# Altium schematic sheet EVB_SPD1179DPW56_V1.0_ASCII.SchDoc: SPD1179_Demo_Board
size A2; Revision: V2.0; SheetNumber: 1; SheetTotal: 1
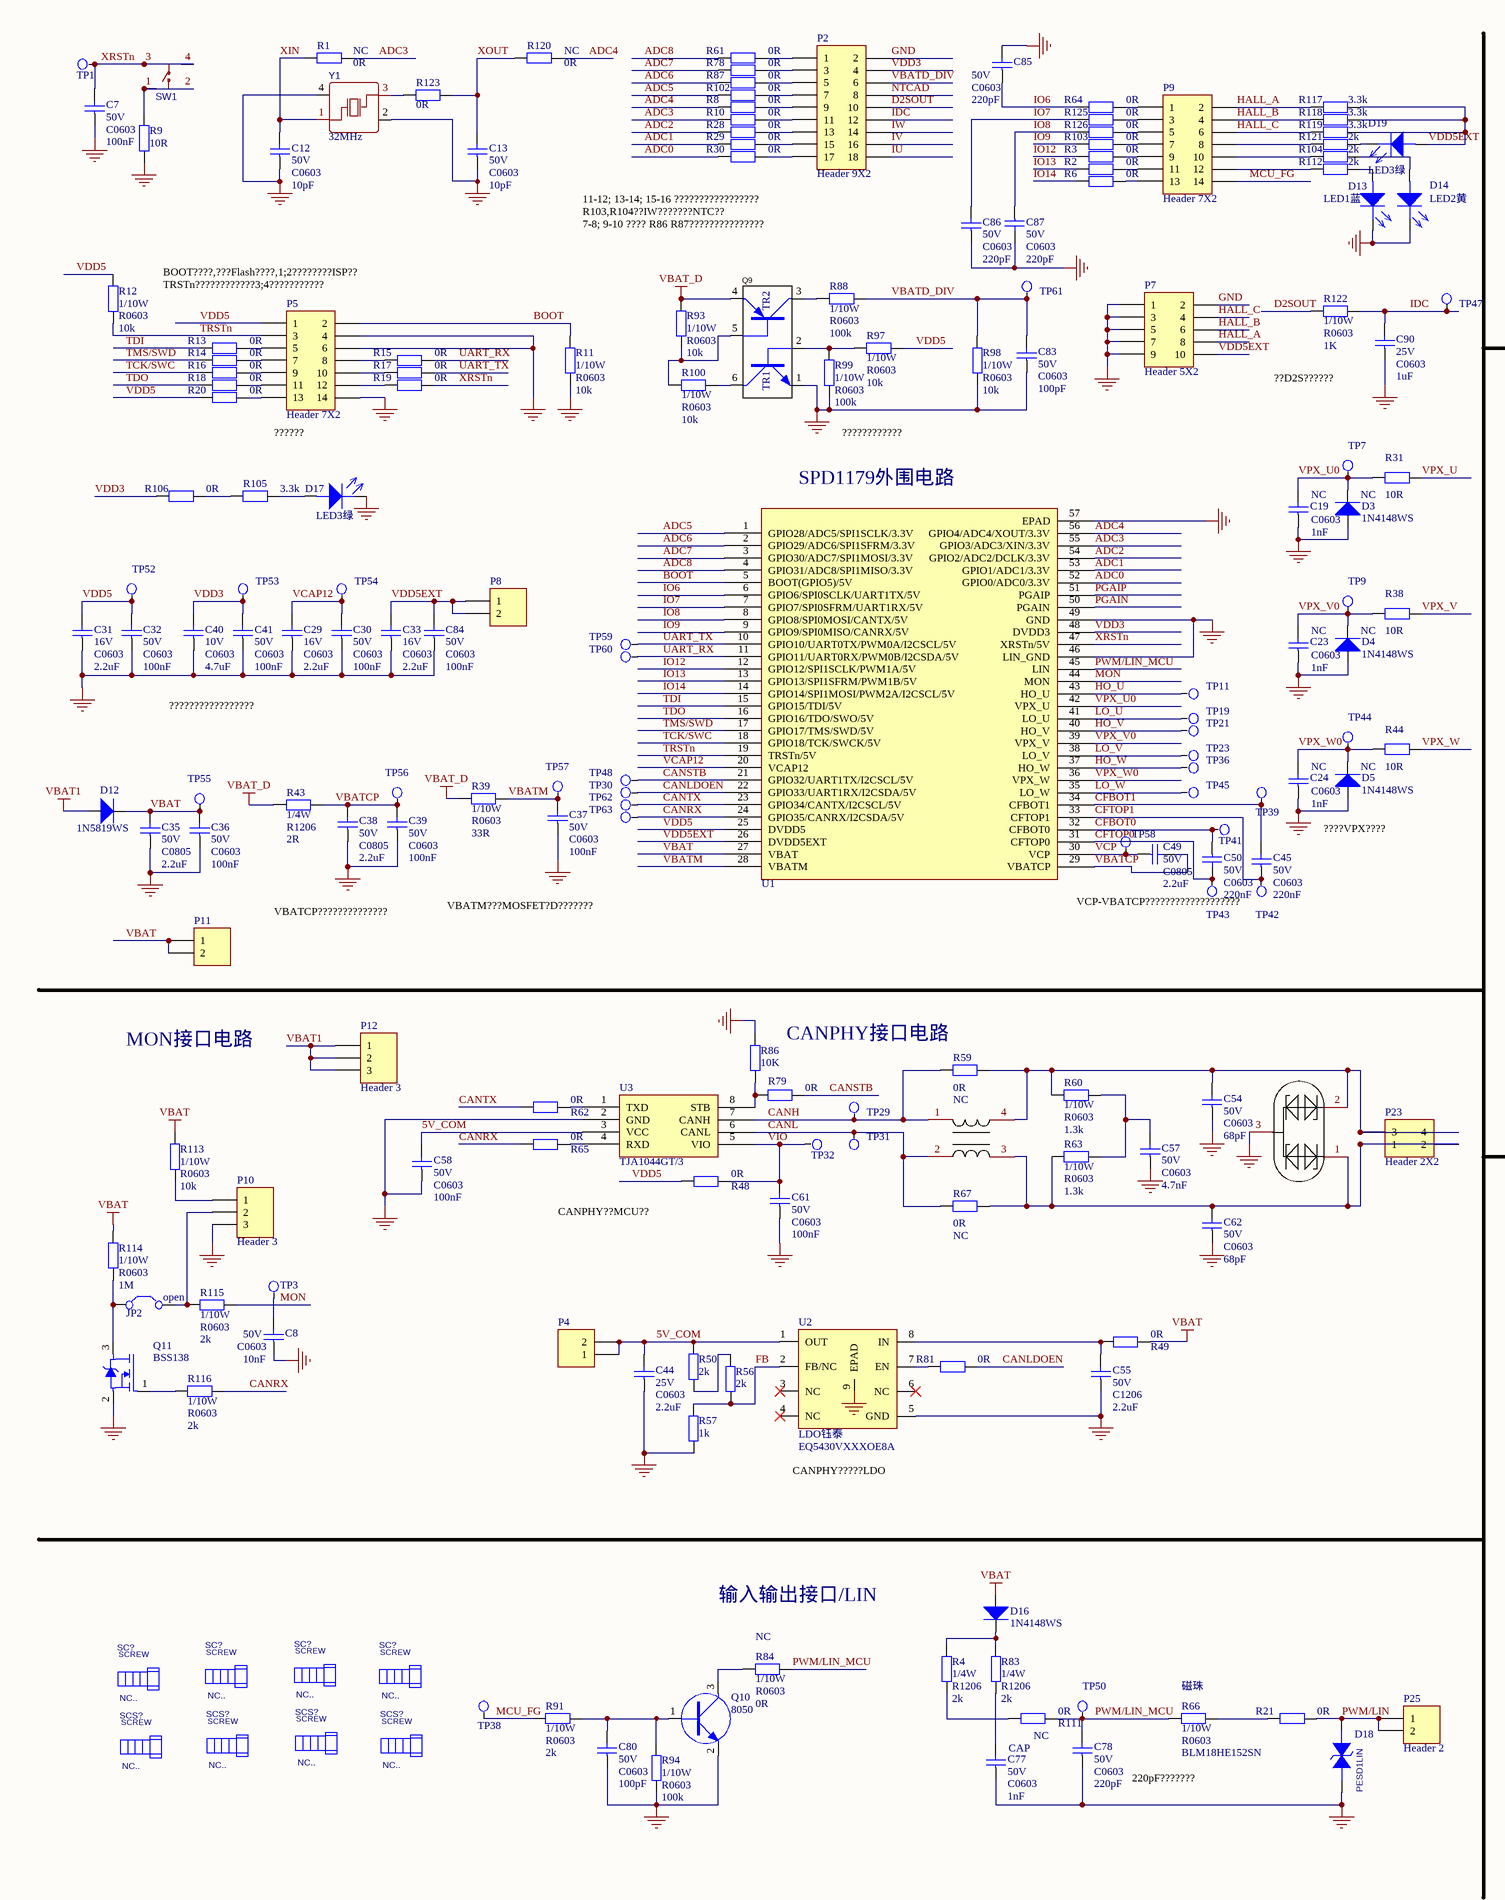
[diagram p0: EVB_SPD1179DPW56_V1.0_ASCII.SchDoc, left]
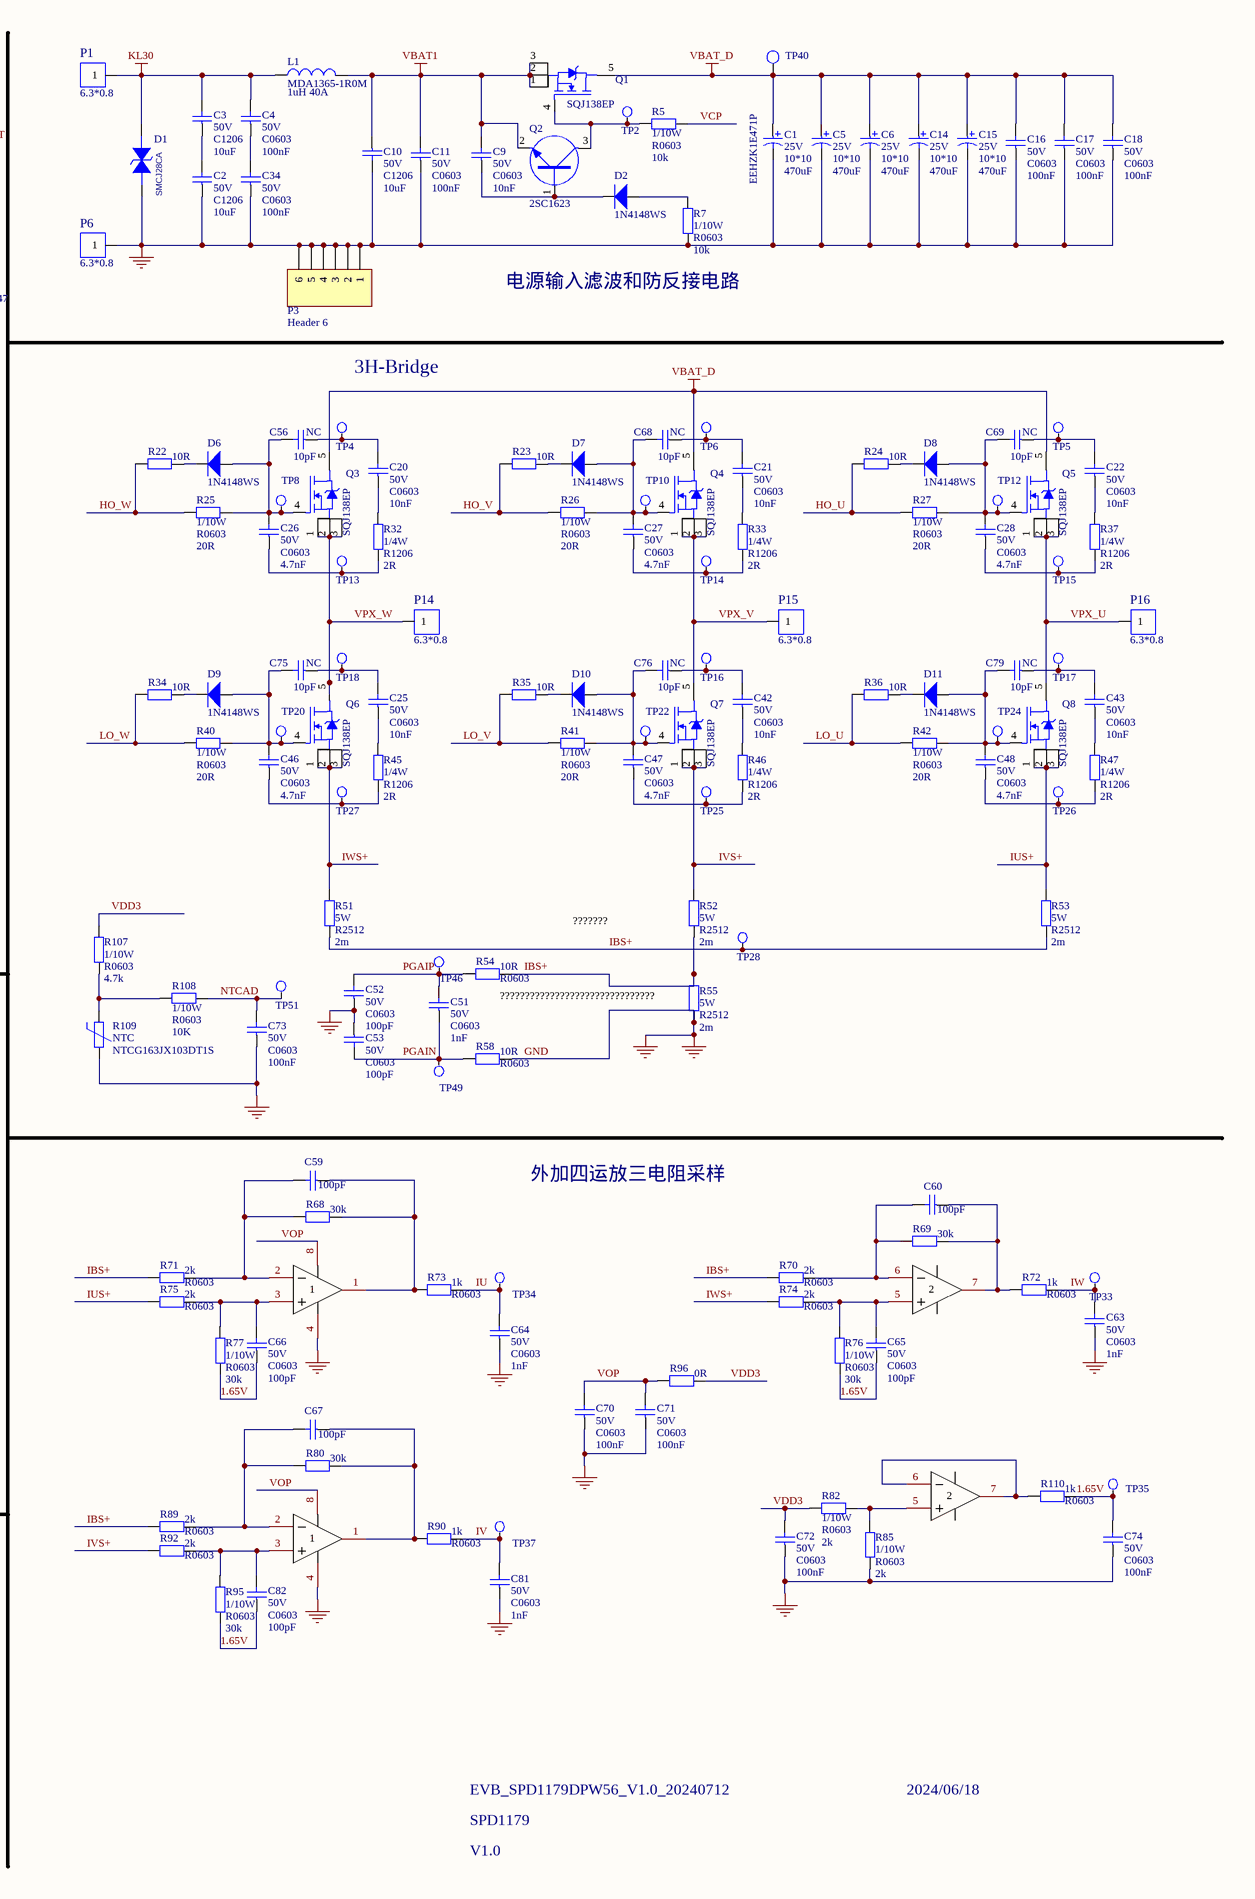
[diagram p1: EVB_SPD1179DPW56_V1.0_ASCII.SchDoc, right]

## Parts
(Parts that share a designator on the sheet are numbered #1, #2 ... from top to bottom, then left to right.)
C1  EEHZK1E471P  value 470uF  Voltage: 25V  Package: 10*10  [CAP-SMD_BD10.0-L10.3-W10.3-FD]
C2  value 10uF  Voltage: 50V  [C1206]  (hidden comment: CAP)
C3  value 10uF  Voltage: 50V  [C1206]  (hidden comment: CAP)
C4  value 100nF  Voltage: 50V  [C0603]  (hidden comment: CAP)
C5  value 470uF  Voltage: 25V  Package: 10*10  [CAP-SMD_BD10.0-L10.3-W10.3-FD]  (hidden comment: EEHZK1E471P)
C6  value 470uF  Voltage: 25V  Package: 10*10  [CAP-SMD_BD10.0-L10.3-W10.3-FD]  (hidden comment: EEHZK1E471P)
C7  value 100nF  Voltage: 50V  [C0603]  (hidden comment: CAP)
C8  value 10nF  Voltage: 50V  [C0603]  (hidden comment: CAP)
C9  value 10nF  Voltage: 50V  [C0603]  (hidden comment: CAP)
C10  value 10uF  Voltage: 50V  [C1206]  (hidden comment: CAP)
C11  value 100nF  Voltage: 50V  [C0603]  (hidden comment: CAP)
C12  value 10pF  Voltage: 50V  [C0603]  (hidden comment: CAP)
C13  value 10pF  Voltage: 50V  [C0603]  (hidden comment: CAP)
C14  value 470uF  Voltage: 25V  Package: 10*10  [CAP-SMD_BD10.0-L10.3-W10.3-FD]  (hidden comment: EEHZK1E471P)
C15  value 470uF  Voltage: 25V  Package: 10*10  [CAP-SMD_BD10.0-L10.3-W10.3-FD]  (hidden comment: EEHZK1E471P)
C16  value 100nF  Voltage: 50V  [C0603]  (hidden comment: CAP)
C17  value 100nF  Voltage: 50V  [C0603]  (hidden comment: CAP)
C18  value 100nF  Voltage: 50V  [C0603]  (hidden comment: CAP)
C19  NC  value 1nF  [C0603]
C20  value 10nF  Voltage: 50V  [C0603]  (hidden comment: CAP)
C21  value 10nF  Voltage: 50V  [C0603]  (hidden comment: CAP)
C22  value 10nF  Voltage: 50V  [C0603]  (hidden comment: CAP)
C23  NC  value 1nF  [C0603]
C24  NC  value 1nF  [C0603]
C25  value 10nF  Voltage: 50V  [C0603]  (hidden comment: CAP)
C26  value 4.7nF  Voltage: 50V  [C0603]  (hidden comment: CAP)
C27  value 4.7nF  Voltage: 50V  [C0603]  (hidden comment: CAP)
C28  value 4.7nF  Voltage: 50V  [C0603]  (hidden comment: CAP)
C29  value 2.2uF  Voltage: 16V  [C0603]  (hidden comment: CAP)
C30  value 100nF  Voltage: 50V  [C0603]  (hidden comment: CAP)
C31  value 2.2uF  Voltage: 16V  [C0603]  (hidden comment: CAP)
C32  value 100nF  Voltage: 50V  [C0603]  (hidden comment: CAP)
C33  value 2.2uF  Voltage: 16V  [C0603]  (hidden comment: CAP)
C34  value 100nF  Voltage: 50V  [C0603]  (hidden comment: CAP)
C35  value 2.2uF  Voltage: 50V  Package: C0805  [0805R]  (hidden comment: CAP)
C36  value 100nF  Voltage: 50V  [C0603]  (hidden comment: CAP)
C37  value 100nF  Voltage: 50V  [C0603]  (hidden comment: CAP)
C38  value 2.2uF  Voltage: 50V  Package: C0805  [0805R]  (hidden comment: CAP)
C39  value 100nF  Voltage: 50V  [C0603]  (hidden comment: CAP)
C40  value 4.7uF  Voltage: 10V  [C0603]  (hidden comment: CAP)
C41  value 100nF  Voltage: 50V  [C0603]  (hidden comment: CAP)
C42  value 10nF  Voltage: 50V  [C0603]  (hidden comment: CAP)
C43  value 10nF  Voltage: 50V  [C0603]  (hidden comment: CAP)
C44  value 2.2uF  Voltage: 25V  [C0603]  (hidden comment: CAP)
C45  value 220nF  Voltage: 50V  [C0603]  (hidden comment: CAP)
C46  value 4.7nF  Voltage: 50V  [C0603]  (hidden comment: CAP)
C47  value 4.7nF  Voltage: 50V  [C0603]  (hidden comment: CAP)
C48  value 4.7nF  Voltage: 50V  [C0603]  (hidden comment: CAP)
C49  value 2.2uF  Voltage: 50V  Package: C0805  [0805R]  (hidden comment: CAP)
C50  value 220nF  Voltage: 50V  [C0603]  (hidden comment: CAP)
C51  value 1nF  Voltage: 50V  [C0603]  (hidden comment: CAP)
C52  value 100pF  Voltage: 50V  [C0603]  (hidden comment: CAP)
C53  value 100pF  Voltage: 50V  [C0603]  (hidden comment: CAP)
C54  value 68pF  Voltage: 50V  [C0603]  (hidden comment: CAP)
C55  value 2.2uF  Voltage: 50V  [C1206]  (hidden comment: CAP)
C56  NC  value 10pF  [C0603]
C57  value 4.7nF  Voltage: 50V  [C0603]  (hidden comment: CAP)
C58  value 100nF  Voltage: 50V  [C0603]  (hidden comment: CAP)
C59  value 100pF  [C0603]  (hidden comment: CAP)
C60  value 100pF  [C0603]  (hidden comment: CAP)
C61  value 100nF  Voltage: 50V  [C0603]  (hidden comment: CAP)
C62  value 68pF  Voltage: 50V  [C0603]  (hidden comment: CAP)
C63  value 1nF  Voltage: 50V  [C0603]  (hidden comment: CAP)
C64  value 1nF  Voltage: 50V  [C0603]  (hidden comment: CAP)
C65  value 100pF  Voltage: 50V  [C0603]  (hidden comment: CAP)
C66  value 100pF  Voltage: 50V  [C0603]  (hidden comment: CAP)
C67  value 100pF  [C0603]  (hidden comment: CAP)
C68  NC  value 10pF  [C0603]
C69  NC  value 10pF  [C0603]
C70  value 100nF  Voltage: 50V  [C0603]  (hidden comment: CAP)
C71  value 100nF  Voltage: 50V  [C0603]  (hidden comment: CAP)
C72  value 100nF  Voltage: 50V  [C0603]  (hidden comment: CAP)
C73  value 100nF  Voltage: 50V  [C0603]  (hidden comment: CAP)
C74  value 100nF  Voltage: 50V  [C0603]  (hidden comment: CAP)
C75  NC  value 10pF  [C0603]
C76  NC  value 10pF  [C0603]
C77  CAP  value 1nF  Voltage: 50V  [C0603]
C78  value 220pF  Voltage: 50V  [C0603]  (hidden comment: CAP)
C79  NC  value 10pF  [C0603]
C80  value 100pF  Voltage: 50V  [C0603]  (hidden comment: CAP)
C81  value 1nF  Voltage: 50V  [C0603]  (hidden comment: CAP)
C82  value 100pF  Voltage: 50V  [C0603]  (hidden comment: CAP)
C83  value 100pF  Voltage: 50V  [C0603]  (hidden comment: CAP)
C84  value 100nF  Voltage: 50V  [C0603]  (hidden comment: CAP)
C85  value 220pF  Voltage: 50V  [C0603]  (hidden comment: CAP)
C86  value 220pF  Voltage: 50V  [C0603]  (hidden comment: CAP)
C87  value 220pF  Voltage: 50V  [C0603]  (hidden comment: CAP)
C90  value 1uF  Voltage: 25V  [C0603]  (hidden comment: CAP)
D1  value SMCJ28CA  [SMC/DO-214AB/Bidirect]
D2  value 1N4148WS  [SODFL2513X100/SOD323F/SC-90]  (hidden comment: DIODE)
D3  NC  value 1N4148WS  [SODFL2513X100/SOD323F/SC-90]
D4  NC  value 1N4148WS  [SODFL2513X100/SOD323F/SC-90]
D5  NC  value 1N4148WS  [SODFL2513X100/SOD323F/SC-90]
D6  value 1N4148WS  [SODFL2513X100/SOD323F/SC-90]
D7  value 1N4148WS  [SODFL2513X100/SOD323F/SC-90]
D8  value 1N4148WS  [SODFL2513X100/SOD323F/SC-90]
D9  value 1N4148WS  [SODFL2513X100/SOD323F/SC-90]
D10  value 1N4148WS  [SODFL2513X100/SOD323F/SC-90]
D11  value 1N4148WS  [SODFL2513X100/SOD323F/SC-90]
D12  value 1N5819WS  [SOD-323_L1.8-W1.3-LS2.5-RD]  (hidden comment: DIODE)
D13  value LED1蓝  [LED0603-R-RD]  (hidden comment: D_LED_0603)
D14  value LED2黄  [LED0603-R-RD]  (hidden comment: D_LED_0603)
D15  PESD1CAN,215  [SOT-23_L2.9-W1.3-P1.90-LS2.4-BR]  (value not drawn)
D16  value 1N4148WS  [SODFL2513X100/SOD323F/SC-90]
D17  value LED3绿  [LED0603-R-RD]  (hidden comment: D_LED_0603)
D18  value PESD1LIN  [SOD-323_L1.7-W1.3-LS2.5-BI]  (hidden comment: TVS)
D19  value LED3绿  [LED0603-R-RD]  (hidden comment: D_LED_0603)
JP2  open  [HDR1X2]
L1  1uH 40A  value MDA1365-1R0M  [IND-SMD_L12.6-W13.5]
L2  ACT45B-510-2P-TL003  [IND-SMD_4P-L4.5-W3.2-TL]  (value not drawn)
P1  Package: 6.3*0.8  [CON_63X08_P1]  (hidden comment: P_CON-1PIN)
P2  Header 9X2  [HDR2X9]
P3  Header 6  [HDR1X6]
P4  (no value)  [HDR1X2]
P5  Header 7X2  [HDR2X7]
P6  Package: 6.3*0.8  [CON_63X08_P1]  (hidden comment: P_CON-1PIN)
P7  Header 5X2  [HDR2X5]
P8  (no value)  [HDR1X2]
P9  Header 7X2  [HDR2X7]
P10  Header 3  [HDR1X3]
P11  (no value)  [HDR1X2]
P12  Header 3  [HDR1X3]
P14  Package: 6.3*0.8  [CON_63X08_P1]  (hidden comment: P_CON-1PIN)
P15  Package: 6.3*0.8  [CON_63X08_P1]  (hidden comment: P_CON-1PIN)
P16  Package: 6.3*0.8  [CON_63X08_P1]  (hidden comment: P_CON-1PIN)
P23  Header 2X2  [HDR2X2]
P25  Header 2  [HDR1X2]
Q1  SQJ138EP  [PowerPAK_SO-8L_3_VIS]
Q2  value 2SC1623  [SOT95P240X110-3/SOT23/TO-236]  (hidden comment: NPN)
Q3  SQJ138EP  [PowerPAK_SO-8L_3_VIS]
Q4  SQJ138EP  [PowerPAK_SO-8L_3_VIS]
Q5  SQJ138EP  [PowerPAK_SO-8L_3_VIS]
Q6  SQJ138EP  [PowerPAK_SO-8L_3_VIS]
Q7  SQJ138EP  [PowerPAK_SO-8L_3_VIS]
Q8  SQJ138EP  [PowerPAK_SO-8L_3_VIS]
Q9  BC847BPN,115  [SOT-363_L2.0-W1.3-P0.65-LS2.1-TL]  (value not drawn)
Q10  value 8050  [SOT95P240X110-3/SOT23/TO-236]  (hidden comment: NPN)
Q11  value BSS138  [SOT95P240X110-3/SOT23/TO-236]  (hidden comment: MOSFET_N-CH)
R1  NC  value 0R  [R0603]
R2  value 0R  [R0603]  (hidden comment: RES)
R3  value 0R  [R0603]  (hidden comment: RES)
R4  value 2k  Power: 1/4W  [R1206]
R5  value 10k  Power: 1/10W  [R0603]  (hidden comment: RES)
R6  value 0R  [R0603]  (hidden comment: RES)
R7  value 10k  Power: 1/10W  [R0603]  (hidden comment: RES)
R8  value 0R  [R0603]  (hidden comment: RES)
R9  value 10R  [R0603]  (hidden comment: RES)
R10  value 0R  [R0603]  (hidden comment: RES)
R11  value 10k  Power: 1/10W  [R0603]  (hidden comment: RES)
R12  value 10k  Power: 1/10W  [R0603]  (hidden comment: RES)
R13  value 0R  [R0603]  (hidden comment: RES)
R14  value 0R  [R0603]  (hidden comment: RES)
R15  value 0R  [R0603]  (hidden comment: RES)
R16  value 0R  [R0603]  (hidden comment: RES)
R17  value 0R  [R0603]  (hidden comment: RES)
R18  value 0R  [R0603]  (hidden comment: RES)
R19  value 0R  [R0603]  (hidden comment: RES)
R20  value 0R  [R0603]  (hidden comment: RES)
R21  value 0R  [R0603]  (hidden comment: RES)
R22  value 10R  [R0603]
R23  value 10R  [R0603]
R24  value 10R  [R0603]
R25  value 20R  Power: 1/10W  [R0603]
R26  value 20R  Power: 1/10W  [R0603]
R27  value 20R  Power: 1/10W  [R0603]
R28  value 0R  [R0603]  (hidden comment: RES)
R29  value 0R  [R0603]  (hidden comment: RES)
R30  value 0R  [R0603]  (hidden comment: RES)
R31  value 10R  [R0603]  (hidden comment: RES)
R32  value 2R  Power: 1/4W  [R1206]  (hidden comment: RES)
R33  value 2R  Power: 1/4W  [R1206]  (hidden comment: RES)
R34  value 10R  [R0603]
R35  value 10R  [R0603]
R36  value 10R  [R0603]
R37  value 2R  Power: 1/4W  [R1206]  (hidden comment: RES)
R38  value 10R  [R0603]  (hidden comment: RES)
R39  value 33R  Power: 1/10W  [R0603]
R40  value 20R  Power: 1/10W  [R0603]
R41  value 20R  Power: 1/10W  [R0603]
R42  value 20R  Power: 1/10W  [R0603]
R43  value 2R  Power: 1/4W  [R1206]  (hidden comment: RES)
R44  value 10R  [R0603]  (hidden comment: RES)
R45  value 2R  Power: 1/4W  [R1206]  (hidden comment: RES)
R46  value 2R  Power: 1/4W  [R1206]  (hidden comment: RES)
R47  value 2R  Power: 1/4W  [R1206]  (hidden comment: RES)
R48  value 0R  [R0603]  (hidden comment: RES)
R49  value 0R  [R0603]  (hidden comment: RES)
R50  value 2k  [R0603]  (hidden comment: RES)
R51  value 2m  Power: 5W  [R2512]  (hidden comment: RES)
R52  value 2m  Power: 5W  [R2512]  (hidden comment: RES)
R53  value 2m  Power: 5W  [R2512]  (hidden comment: RES)
R54  value 10R  [R0603]  (hidden comment: RES)
R55  value 2m  Power: 5W  [R2512]  (hidden comment: RES)
R56  value 2k  [R0603]  (hidden comment: RES)
R57  value 1k  [R0603]  (hidden comment: RES)
R58  value 10R  [R0603]  (hidden comment: RES)
R59  NC  value 0R  [R0402]
R60  value 1.3k  Power: 1/10W  [R0603]  (hidden comment: RES)
R61  value 0R  [R0603]  (hidden comment: RES)
R62  value 0R  [R0603]  (hidden comment: RES)
R63  value 1.3k  Power: 1/10W  [R0603]  (hidden comment: RES)
R64  value 0R  [R0603]  (hidden comment: RES)
R65  value 0R  [R0603]  (hidden comment: RES)
R66  磁珠  value BLM18HE152SN  Power: 1/10W  [R0603]
R67  NC  value 0R  [R0402]
R68  value 30k  [R0603]  (hidden comment: RES)
R69  value 30k  [R0603]  (hidden comment: RES)
R70  value 2k  [R0603]  (hidden comment: RES)
R71  value 2k  [R0603]  (hidden comment: RES)
R72  value 1k  [R0603]  (hidden comment: RES)
R73  value 1k  [R0603]  (hidden comment: RES)
R74  value 2k  [R0603]  (hidden comment: RES)
R75  value 2k  [R0603]  (hidden comment: RES)
R76  value 30k  Power: 1/10W  [R0603]  (hidden comment: RES)
R77  value 30k  Power: 1/10W  [R0603]  (hidden comment: RES)
R78  value 0R  [R0603]  (hidden comment: RES)
R79  value 0R  [R0603]  (hidden comment: RES)
R80  value 30k  [R0603]  (hidden comment: RES)
R81  value 0R  [R0603]  (hidden comment: RES)
R82  value 2k  Power: 1/10W  [R0603]  (hidden comment: RES)
R83  value 2k  Power: 1/4W  [R1206]
R84  NC  value 0R  Power: 1/10W  [R0603]
R85  value 2k  Power: 1/10W  [R0603]  (hidden comment: RES)
R86  value 10K  [R0603]  (hidden comment: RES)
R87  value 0R  [R0603]  (hidden comment: RES)
R88  value 100k  Power: 1/10W  [R0603]  (hidden comment: RES)
R89  value 2k  [R0603]  (hidden comment: RES)
R90  value 1k  [R0603]  (hidden comment: RES)
R91  value 2k  Power: 1/10W  [R0603]  (hidden comment: RES)
R92  value 2k  [R0603]  (hidden comment: RES)
R93  value 10k  Power: 1/10W  [R0603]  (hidden comment: RES)
R94  value 100k  Power: 1/10W  [R0603]  (hidden comment: RES)
R95  value 30k  Power: 1/10W  [R0603]  (hidden comment: RES)
R96  value 0R  [R0603]
R97  value 10k  Power: 1/10W  [R0603]  (hidden comment: RES)
R98  value 10k  Power: 1/10W  [R0603]  (hidden comment: RES)
R99  value 100k  Power: 1/10W  [R0603]  (hidden comment: RES)
R100  value 10k  Power: 1/10W  [R0603]  (hidden comment: RES)
R102  value 0R  [R0603]  (hidden comment: RES)
R103  value 0R  [R0603]  (hidden comment: RES)
R104  value 2k  [R0603]  (hidden comment: RES)
R105  value 3.3k  [R0603]  (hidden comment: RES)
R106  value 0R  [R0603]  (hidden comment: RES)
R107  value 4.7k  Power: 1/10W  [R0603]  (hidden comment: RES)
R108  value 10K  Power: 1/10W  [R0603]  (hidden comment: RES)
R109  NTC  value NTCG163JX103DT1S  [R0603]
R110  value 1k  [R0603]  (hidden comment: RES)
R111  NC  value 0R  [R0603]
R112  value 2k  [R0603]  (hidden comment: RES)
R113  value 10k  Power: 1/10W  [R0603]  (hidden comment: RES)
R114  value 1M  Power: 1/10W  [R0603]
R115  value 2k  Power: 1/10W  [R0603]  (hidden comment: RES)
R116  value 2k  Power: 1/10W  [R0603]  (hidden comment: RES)
R117  value 3.3k  [R0603]  (hidden comment: RES)
R118  value 3.3k  [R0603]  (hidden comment: RES)
R119  value 3.3k  [R0603]  (hidden comment: RES)
R120  NC  value 0R  [R0603]
R121  value 2k  [R0603]  (hidden comment: RES)
R122  value 1K  Power: 1/10W  [R0603]  (hidden comment: RES)
R123  value 0R  [R0603]  (hidden comment: RES)
R125  value 0R  [R0603]  (hidden comment: RES)
R126  value 0R  [R0603]  (hidden comment: RES)
SC?#1  value NC..  [SCREW_HOLE_Φ3_plated_wo keepout]  (hidden comment: SCREW)
SC?#2  value NC..  [SCREW_HOLE_Φ3_plated_wo keepout]  (hidden comment: SCREW)
SC?#3  value NC..  [SCREW_HOLE_Φ3_plated_wo keepout]  (hidden comment: SCREW)
SC?#4  value NC..  [SCREW_HOLE_Φ3_plated_wo keepout]  (hidden comment: SCREW)
SCS?#1  value NC..  [SCREW_SILK2]  (hidden comment: SCREW)
SCS?#2  value NC..  [SCREW_SILK2]  (hidden comment: SCREW)
SCS?#3  value NC..  [SCREW_SILK2]  (hidden comment: SCREW)
SCS?#4  value NC..  [SCREW_SILK2]  (hidden comment: SCREW)
SW1  TS-1095PD-A6B2-D2  [KEY-TH_4P-L6.0-W6.0-P3.90-LS6.5]  (value not drawn)
TP1  TEST-Point  [TP-1.0]  (value not drawn)
TP2  TEST-Point  [TP-1.0]  (value not drawn)
TP3  TEST-Point  [TP-1.0]  (value not drawn)
TP4  TEST-Point  [TP-1.0]  (value not drawn)
TP5  TEST-Point  [TP-1.0]  (value not drawn)
TP6  TEST-Point  [TP-1.0]  (value not drawn)
TP7  TEST-Point  [TP-1.0]  (value not drawn)
TP8  TEST-Point  [TP-1.0]  (value not drawn)
TP9  TEST-Point  [TP-1.0]  (value not drawn)
TP10  TEST-Point  [TP-1.0]  (value not drawn)
TP11  TEST-Point  [TP-1.0]  (value not drawn)
TP12  TEST-Point  [TP-1.0]  (value not drawn)
TP13  TEST-Point  [TP-1.0]  (value not drawn)
TP14  TEST-Point  [TP-1.0]  (value not drawn)
TP15  TEST-Point  [TP-1.0]  (value not drawn)
TP16  TEST-Point  [TP-1.0]  (value not drawn)
TP17  TEST-Point  [TP-1.0]  (value not drawn)
TP18  TEST-Point  [TP-1.0]  (value not drawn)
TP19  TEST-Point  [TP-1.0]  (value not drawn)
TP20  TEST-Point  [TP-1.0]  (value not drawn)
TP21  TEST-Point  [TP-1.0]  (value not drawn)
TP22  TEST-Point  [TP-1.0]  (value not drawn)
TP23  TEST-Point  [TP-1.0]  (value not drawn)
TP24  TEST-Point  [TP-1.0]  (value not drawn)
TP25  TEST-Point  [TP-1.0]  (value not drawn)
TP26  TEST-Point  [TP-1.0]  (value not drawn)
TP27  TEST-Point  [TP-1.0]  (value not drawn)
TP28  TEST-Point  [TP-1.0]  (value not drawn)
TP29  TEST-Point  [TP-1.0]  (value not drawn)
TP30  TEST-Point  [TP-1.0]  (value not drawn)
TP31  TEST-Point  [TP-1.0]  (value not drawn)
TP32  TEST-Point  [TP-1.0]  (value not drawn)
TP33  TEST-Point  [TP-1.0]  (value not drawn)
TP34  TEST-Point  [TP-1.0]  (value not drawn)
TP35  TEST-Point  [TP-1.0]  (value not drawn)
TP36  TEST-Point  [TP-1.0]  (value not drawn)
TP37  TEST-Point  [TP-1.0]  (value not drawn)
TP38  TEST-Point  [TP-1.0]  (value not drawn)
TP39  TEST-Point  [TP-1.0]  (value not drawn)
TP40  TEST-SMD  [TEST-SMD_L2.7-W1.0]  (value not drawn)
TP41  TEST-Point  [TP-1.0]  (value not drawn)
TP42  TEST-Point  [TP-1.0]  (value not drawn)
TP43  TEST-Point  [TP-1.0]  (value not drawn)
TP44  TEST-Point  [TP-1.0]  (value not drawn)
TP45  TEST-Point  [TP-1.0]  (value not drawn)
TP46  TEST-Point  [TP-1.0]  (value not drawn)
TP47  TEST-Point  [TP-1.0]  (value not drawn)
TP48  TEST-Point  [TP-1.0]  (value not drawn)
TP49  TEST-Point  [TP-1.0]  (value not drawn)
TP50  TEST-Point  [TP-1.0]  (value not drawn)
TP51  TEST-Point  [TP-1.0]  (value not drawn)
TP52  TEST-Point  [TP-1.0]  (value not drawn)
TP53  TEST-Point  [TP-1.0]  (value not drawn)
TP54  TEST-Point  [TP-1.0]  (value not drawn)
TP55  TEST-Point  [TP-1.0]  (value not drawn)
TP56  TEST-Point  [TP-1.0]  (value not drawn)
TP57  TEST-Point  [TP-1.0]  (value not drawn)
TP58  TEST-Point  [TP-1.0]  (value not drawn)
TP59  TEST-Point  [TP-1.0]  (value not drawn)
TP60  TEST-Point  [TP-1.0]  (value not drawn)
TP61  TEST-Point  [TP-1.0]  (value not drawn)
TP62  TEST-Point  [TP-1.0]  (value not drawn)
TP63  TEST-Point  [TP-1.0]  (value not drawn)
U1  SPD1179  [QFN-56-0.5_B]  (value not drawn)
U2  LDO钰泰  value EQ5430VXXXOE8A  [ESOP-8_L4.9-W3.9-P1.27-LS6.0-BL-EP]
U3  TJA1044GT/3  [SOIC-8_L4.9-W3.9-P1.27-LS6.0-BL]
U4  AD8542ARZ-REEL7  [SOIC-8_L4.9-W3.9-P1.27-LS6.0-BL]  (value not drawn)  (parts A,B of 2)
U5  AD8542ARZ-REEL7  [SOIC-8_L4.9-W3.9-P1.27-LS6.0-BL]  (value not drawn)  (parts A,B of 2)
Y1  32MHz  [CRYSTAL-SMD_4P-L3.2-W2.5-BL]

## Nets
GND: C1.2 C2.1 C5.2 C6.2 C7.1 C8.1 C10.2 C11.1 C12.1 C13.1 C14.2 C15.2 C16.1 C17.1 C18.1 C19.1 C23.1 C24.1 C29.1 C30.1 C31.1 C32.1 C33.1 C34.1 C35.1 C36.1 C37.1 C38.1 C39.1 C40.1 C41.1 C44.1 C52.1 C53.1 C54.1 C55.1 C57.1 C58.1 C61.1 C62.1 C63.1 C64.1 C70.1 C71.1 C72.1 C73.1 C74.1 C77.1 C78.1 C80.1 C81.1 C83.1 C84.1 C85.2 C86.1 C87.2 C90.1 D1.1(CATHODE1) D3.2(A) D4.2(A) D5.2(A) D13.2(K) D14.2(K) D15.3 D17.2(K) D18.1(CATHODE1) P2.2 P3.1 P3.2 P3.3 P3.4 P3.5 P3.6 P5.4 P5.6 P5.14 P6.1 P7.1 P7.2 P7.3 P7.5 P7.7 P7.9 P10.3 Q9.1(N_E) Q10.2(2E) Q11.2(SOURCE) R7.1 R9.2 R11.1 R55.1 R57.1 R58.1 R85.2 R86.1 R94.1 R98.2 R99.1 R109.2 U1.46(LIN_GND) U1.49(GND) U1.57(EPAD) U2.5(GND) U2.9(EPAD) U3.2(GND) U4.4(V-) U5.4(V-) Y1.2(GND) Y1.4(GND)  [also labelled PGND]
KL30: C3.2 C4.2 D1.2(CATHODE2) L1.1 P1.1
VBAT: C35.2 C36.2 D12.1(K) D16.2(A) P11.1 P11.2 R49.1 R113.2 R114.1 TP55.1 U1.27(VBAT)
VBAT1: C9.2 C10.1 C11.2 D12.2(A) L1.2 P12.1 P12.2 P12.3 Q1.1(SOURCE) Q1.2(SOURCE) Q1.3(SOURCE) Q2.2(2E)
VBAT_D: C1.1 C5.1 C6.1 C14.1 C15.1 C16.2 C17.2 C18.2 Q1.5(DRAIN) Q3.5(DRAIN) Q4.5(DRAIN) Q5.5(DRAIN) Q9.4(P_E) R39.2 R43.1 R93.1 TP40.1
1.65V: C65.1 C66.1 C74.2 C82.1 R76.1 R77.1 R95.1 R110.1 TP35.1
5V_COM: C44.2 C58.2 P4.1 P4.2 R50.2 U2.1(OUT) U3.3(VCC)
ADC0: R30.2 U1.52(GPIO0/ADC0/3.3V)
ADC1: R29.2 U1.53(GPIO1/ADC1/3.3V)
ADC2: R28.2 U1.54(GPIO2/ADC2/DCLK/3.3V)
ADC3: R1.2 R10.2 U1.55(GPIO3/ADC3/XIN/3.3V)
ADC4: R8.2 R120.2 U1.56(GPIO4/ADC4/XOUT/3.3V)
ADC5: R102.2 U1.1(GPIO28/ADC5/SPI1SCLK/3.3V)
ADC6: R87.2 U1.2(GPIO29/ADC6/SPI1SFRM/3.3V)
ADC7: R78.2 U1.3(GPIO30/ADC7/SPI1MOSI/3.3V)
ADC8: R61.2 U1.4(GPIO31/ADC8/SPI1MISO/3.3V)
BOOT: P5.2 R11.2 U1.5(BOOT(GPIO5)/5V)
CANH: L2.1 R59.1 TP29.1 U3.7(CANH)
CANL: L2.2 R67.1 TP31.1 U3.6(CANL)
CANLDOEN: R81.1 TP30.1 U1.22(GPIO33/UART1RX/I2CSDA/5V)
CANRX: R65.2 R116.1 TP63.1 U1.24(GPIO35/CANRX/I2CSDA/5V)
CANSTB: R79.1 TP48.1 U1.21(GPIO32/UART1TX/I2CSCL/5V)
CANTX: R62.2 TP62.1 U1.23(GPIO34/CANTX/I2CSCL/5V)
CFBOT0: C50.1 TP41.1 U1.32(CFBOT0)
CFBOT1: C45.2 TP39.1 U1.34(CFBOT1)
CFTOP0: C50.2 TP43.1 U1.31(CFTOP0)
CFTOP1: C45.1 TP42.1 U1.33(CFTOP1)
D2SOUT: P2.10 R122.2
FB: R56.1 R57.2 U2.2(FB/NC)
HALL_A: P7.8 P9.2 R117.1
HALL_B: P7.6 P9.4 R118.1
HALL_C: P7.4 P9.6 R119.1
HO_U: R24.2 R27.2 TP11.1 U1.43(HO_U)
HO_V: R23.2 R26.2 TP21.1 U1.40(HO_V)
HO_W: R22.2 R25.2 TP36.1 U1.37(HO_W)
IBS+: R51.1 R52.1 R53.1 R54.1 R55.2 R70.2 R71.2 R89.2 TP28.1
IDC: C90.2 P2.12 R122.1 TP47.1
IO6: C85.1 R64.2 U1.6(GPIO6/SPI0SCLK/UART1TX/5V)
IO7: C86.2 R125.2 U1.7(GPIO7/SPI0SFRM/UART1RX/5V)
IO8: C87.1 R126.2 U1.8(GPIO8/SPI0MOSI/CANTX/5V)
IO9: R103.2 U1.9(GPIO9/SPI0MISO/CANRX/5V)
IO12: R3.2 U1.12(GPIO12/SPI1SCLK/PWM1A/5V)
IO13: R2.2 U1.13(GPIO13/SPI1SFRM/PWM1B/5V)
IO14: R6.2 U1.14(GPIO14/SPI1MOSI/PWM2A/I2CSCL/5V)
IU: C64.2 P2.18 R73.1 TP34.1
IUS+: Q8.1(SOURCE) Q8.2(SOURCE) Q8.3(SOURCE) R53.2 R75.2
IV: C81.2 P2.16 R90.1 TP37.1
IVS+: Q7.1(SOURCE) Q7.2(SOURCE) Q7.3(SOURCE) R52.2 R92.2
IW: C63.2 P2.14 R72.1 TP33.1
IWS+: Q6.1(SOURCE) Q6.2(SOURCE) Q6.3(SOURCE) R51.2 R74.2
LO_U: R36.2 R42.2 TP19.1 U1.41(LO_U)
LO_V: R35.2 R41.2 TP23.1 U1.38(LO_V)
LO_W: R34.2 R40.2 TP45.1 U1.35(LO_W)
MCU_FG: P9.14 R91.2 TP38.1
MON: R115.1 U1.44(MON)
NTCAD: C73.2 P2.8 R108.2 TP51.1
PGAIN: C51.1 C53.2 R58.2 TP49.1 U1.50(PGAIN)
PGAIP: C51.2 C52.2 R54.2 TP46.1 U1.51(PGAIP)
PWM/LIN: D18.2(CATHODE2) P25.1 P25.2 R21.1
PWM/LIN_MCU: C78.2 R66.2 R84.1 R111.1 TP50.1 U1.45(LIN)
TCK/SWC: R16.2 U1.18(GPIO18/TCK/SWCK/5V)
TDI: R13.2 U1.15(GPIO15/TDI/5V)
TDO: R18.2 U1.16(GPIO16/TDO/SWO/5V)
TMS/SWD: R14.2 U1.17(GPIO17/TMS/SWD/5V)
TRSTn: P5.3 R12.1 U1.19(TRSTn/5V)
UART_RX: R15.1 TP60.1 U1.11(GPIO11/UART0RX/PWM0B/I2CSDA/5V)
UART_TX: R17.1 TP59.1 U1.10(GPIO10/UART0TX/PWM0A/I2CSCL/5V)
VBATCP: C38.2 C39.2 C49.2 R43.2 TP56.1 U1.29(VBATCP)
VBATD_DIV: C83.2 P2.6 R88.1 R98.1 TP61.1
VBATM: C37.2 R39.1 TP57.1 U1.28(VBATM)
VCAP12: C29.2 C30.2 TP54.1 U1.20(VCAP12)
VCP: C49.1 R5.1 TP58.1 U1.30(VCP)
VDD3: C40.2 C41.2 C72.2 P2.4 R82.1 R96.1 R106.2 R107.2 TP53.1 U1.48(DVDD3)
VDD5: C31.2 C32.2 P5.1 R12.2 R20.2 R48.2 R97.1 TP52.1 U1.25(DVDD5)
VDD5EXT: C33.2 C84.2 D19.1(A) P7.1(10) P8.1 P8.2 R117.2 R118.2 R119.2 U1.26(DVDD5EXT)
VIO: C61.2 R48.1 TP32.1 U3.5(VIO)
VOP: C70.2 C71.2 R96.2 U4.8(V+) U5.8(V+)
VPX_U: P16.1 Q5.1(SOURCE) Q5.2(SOURCE) Q5.3(SOURCE) Q8.5(DRAIN) R31.1
VPX_U0: C19.2 D3.1(K) R31.2 TP7.1 U1.42(VPX_U)
VPX_V: P15.1 Q4.1(SOURCE) Q4.2(SOURCE) Q4.3(SOURCE) Q7.5(DRAIN) R38.1
VPX_V0: C23.2 D4.1(K) R38.2 TP9.1 U1.39(VPX_V)
VPX_W: P14.1 Q3.1(SOURCE) Q3.2(SOURCE) Q3.3(SOURCE) Q6.5(DRAIN) R44.1
VPX_W0: C24.2 D5.1(K) R44.2 TP44.1 U1.36(VPX_W)
XIN: C12.2 R1.1 Y1.1(OSC1)
XOUT: C13.2 R120.1 R123.2
XRSTn: C7.2 R19.1 SW1.3 SW1.4 TP1.1 U1.47(XRSTn/5V)
NetC2_2: C2.2 C3.1
NetC4_1: C4.1 C34.2
NetC8_2: C8.2 TP3.1
NetC9_1: C9.1 D2.1(K) Q2.1(1B)
NetC20_1: C20.1 R32.1
NetC20_2: C20.2 C56.1 TP4.1
NetC21_1: C21.1 R33.1
NetC21_2: C21.2 C68.1 TP6.1
NetC22_1: C22.1 R37.1
NetC22_2: C22.2 C69.1 TP5.1
NetC25_1: C25.1 R45.1
NetC25_2: C25.2 C75.1 TP18.1
NetC26_1: C26.1 R32.2 TP13.1
NetC26_2: C26.2 C56.2 D6.2(A) Q3.4(GATE) R25.1 TP8.1
NetC27_1: C27.1 R33.2 TP14.1
NetC27_2: C27.2 C68.2 D7.2(A) Q4.4(GATE) R26.1 TP10.1
NetC28_1: C28.1 R37.2 TP15.1
NetC28_2: C28.2 C69.2 D8.2(A) Q5.4(GATE) R27.1 TP12.1
NetC42_1: C42.1 R46.1
NetC42_2: C42.2 C76.1 TP16.1
NetC43_1: C43.1 R47.1
NetC43_2: C43.2 C79.1 TP17.1
NetC46_1: C46.1 R45.2 TP27.1
NetC46_2: C46.2 C75.2 D9.2(A) Q6.4(GATE) R40.1 TP20.1
NetC47_1: C47.1 R46.2 TP25.1
NetC47_2: C47.2 C76.2 D10.2(A) Q7.4(GATE) R41.1 TP22.1
NetC48_1: C48.1 R47.2 TP26.1
NetC48_2: C48.2 C79.2 D11.2(A) Q8.4(GATE) R42.1 TP24.1
NetC54_2: C54.2 D15.2 L2.4 P23.3 P23.4 R59.2 R60.2
NetC55_2: C55.2 R49.2 U2.8(IN)
NetC57_2: C57.2 R60.1 R63.1
NetC59_1: C59.1 R68.1 R73.2 U4.1(OUT)
NetC59_2: C59.2 R68.2 R71.1 U4.2(IN-)
NetC60_1: C60.1 R69.1 R72.2 U4.7(OUT)
NetC60_2: C60.2 R69.2 R70.1 U4.6(IN-)
NetC62_2: C62.2 D15.1 L2.3 P23.1 P23.2 R63.2 R67.2
NetC65_2: C65.2 R74.1 R76.2 U4.5(IN+)
NetC66_2: C66.2 R75.1 R77.2 U4.3(IN+)
NetC67_1: C67.1 R80.1 R90.2 U5.1(OUT)
NetC67_2: C67.2 R80.2 R89.1 U5.2(IN-)
NetC77_2: C77.2 R83.1
NetC80_2: C80.2 Q10.1(1B) R91.1 R94.2
NetC82_2: C82.2 R92.1 R95.2 U5.3(IN+)
NetD2_2: D2.2(A) R7.2
NetD6_1: D6.1(K) R22.1
NetD7_1: D7.1(K) R23.1
NetD8_1: D8.1(K) R24.1
NetD9_1: D9.1(K) R34.1
NetD10_1: D10.1(K) R35.1
NetD11_1: D11.1(K) R36.1
NetD13_1: D13.1(A) R112.2
NetD14_1: D14.1(A) R104.2
NetD16_1: D16.1(K) R4.2 R83.2
NetD17_1: D17.1(A) R105.2
NetD19_2: D19.2(K) R121.2
NetJP2_1: JP2.1(C1) P10.2 R115.2
NetJP2_2: JP2.2(C2) Q11.3(DRAIN) R114.2
NetP2_1: P2.1 R61.1
NetP2_3: P2.3 R78.1
NetP2_5: P2.5 R87.1
NetP2_7: P2.7 R102.1
NetP2_9: P2.9 R8.1
NetP2_11: P2.11 R10.1
NetP2_13: P2.13 R28.1
NetP2_15: P2.15 R29.1
NetP2_17: P2.17 R30.1
NetP5_5: P5.5 R13.1
NetP5_7: P5.7 R14.1
NetP5_8: P5.8 R15.2
NetP5_9: P5.9 R16.1
NetP5_10: P5.10 R17.2
NetP5_11: P5.11 R18.1
NetP5_12: P5.12 R19.2
NetP5_13: P5.13 R20.1
NetP9_1: P9.1 R64.1
NetP9_3: P9.3 R125.1
NetP9_5: P9.5 R126.1
NetP9_7: P9.7 R103.1
NetP9_8: P9.8 R121.1
NetP9_9: P9.9 R3.1
NetP9_10: P9.10 R104.1
NetP9_11: P9.11 R2.1
NetP9_12: P9.12 R112.1
NetP9_13: P9.13 R6.1
NetP10_1: P10.1 R113.1
NetQ1_4: Q1.4(GATE) Q2.3(3C) R5.2 TP2.1
NetQ9_2: Q9.2(N_B) R97.2 R99.2
NetQ9_3: Q9.3(P_C) R88.2
NetQ9_5: Q9.5(P_B) R93.2 R100.1
NetQ9_6: Q9.6(N_C) R100.2
NetQ10_3: Q10.3(3C) R84.2
NetQ11_1: Q11.1(GATE) R116.2
NetR4_1: R4.1 R111.2
NetR9_1: R9.1 SW1.1 SW1.2
NetR21_2: R21.2 R66.1
NetR50_1: R50.1 R56.2
NetR62_1: R62.1 U3.1(TXD)
NetR65_1: R65.1 U3.4(RXD)
NetR79_2: R79.2 R86.2 U3.8(STB)
NetR81_2: R81.2 U2.7(EN)
NetR82_2: R82.2 R85.1 U5.5(IN+)
NetR105_1: R105.1 R106.1
NetR107_1: R107.1 R108.1 R109.1
NetR110_2: R110.2 U5.6(IN-) U5.7(OUT)
NetR123_1: R123.1 Y1.3(OSC2)

Not connected (* = marked no-connect by the designer): U2 3(NC)* 4(NC)* 6(NC)*

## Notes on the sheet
- 11-12; 13-14; 15-16 ?????????????????
  R103,R104??IW???????NTC??
  7-8; 9-10 ???? R86 R87???????????????
- (near P5) BOOT????,???Flash????,1;2????????ISP??
  TRSTn????????????3;4???????????
- 电源输入滤波和防反接电路
- (near C90) ??D2S??????
- 3H-Bridge
- (near P5) ??????
- ????????????
- (near U1) SPD1179外围电路
- ?????????????????
- ????VPX????
- VBATCP??????????????
- VBATM???MOSFET?D???????
- VCP-VBATCP???????????????????
- (near R52) ???????
- MON接口电路
- CANPHY接口电路
- ???????????????????????????????
- (near R48) CANPHY??MCU??
- 外加四运放三电阻采样
- (near U2) CANPHY?????LDO
- 输入输出接口/LIN
- 220pF???????
- EVB_SPD1179DPW56_V1.0_20240712
- 2024/06/18
- SPD1179
- V1.0

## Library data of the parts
C1 C5 C6 C14 C15 = CE_50V_220uF_10*10: Capacitor polarized
C2 C3 C10 C35 C38 C55 = C_1206_10%_1: MLCC
C4 C7-C9 C11-C13 C16-C18 C20-C22 C25-C34 C36 C37 C39-C54 C57 C58 C61-C66 C70-C74 C77 C78 C80-C87 C90 = C_0603_10%_1: MLCC
C19 C23 C24 C56 C59 C60 C67-C69 C75 C76 C79 = C_0603_10%_1: MLCC; Voltage: 50V
D1 = D_TVS_SMC: TVS Bidirectional
D2-D11 D16 = D_1N4148WS: Diode SOD323
D12 = D_SMA
D15 = D_PESD1CAN,215: Manufacturer: Nexperia(安世); Add into BOM: yes; Polarity: Bidirectional; Voltage - Reverse Standoff (Typ): 24V; Voltage - Breakdown (Min): 25.4V; Voltage - Clamping (Max) @ Ipp: 70V
D18 = D_ESD_BI_SOD323: ESD TVS Bidirectional
JP2 = Jumper: Jumper Wire
L1 = L_SER2000
L2 = L_ACT45B-510-2P-TL003: Manufacturer: TDK; Add into BOM: yes; Number of Lines: 2; Impedance @ Frequency: 2.8kΩ@10MHz; Inductance @ Frequency: 51uH@100kHz; Current Rating: 200mA
P1 P6 P14-P16 = P_CON-1PIN: Insert terminal,快接端子 6.3mm*0.8厚 插片
P2 = Header 9X2: Header, 9-Pin, Dual row
P3 = Header 6: Header, 6-Pin
P4 P8 P11 P25 = Header 2: Header, 2-Pin
P5 P9 = Header 7X2: Header, 7-Pin, Dual row
P7 = Header 5X2: Header, 5-Pin, Dual row
P10 P12 = Header 3: Header, 3-Pin
P23 = Header 2X2: Header, 2-Pin, Dual row
Q1 Q3-Q8 = Q_N_DFN-8L_5*6: N-CHANNEL; Id: 330A; Vds: 40V
Q2 Q10 = Q_8050
Q9 = Q_BC847BPN,115: Manufacturer: Nexperia(安世); Add into BOM: yes; Transistor Type: NPN+PNP; Collector Current (Ic): 100mA; Collector-Emitter Breakdown Voltage (Vceo): 45V; Power Dissipation (Pd): 300mW
Q11 = Q_BSS138: N-CHANNEL
R1-R3 R6 R8-R10 R13-R24 R28-R31 R34-R36 R38 R44 R48-R50 R54 R56-R58 R61 R62 R64 R65 R68-R75 R78-R81 R86 R87 R89 R90 R92 R96 R102-R106 R110-R112 R117-R121 R123 R125 R126 = R_0603_1/10W_1%_1: Thick film; Power: 1/10W
R4 R32 R33 R37 R43 R45-R47 R83 = R_1206_1/4W_1%_1: Thick film
R5 R7 R11 R12 R25-R27 R39-R42 R60 R63 R66 R76 R77 R82 R84 R85 R88 R91 R93-R95 R97-R100 R107 R108 R113-R116 R122 = R_0603_1/10W_1%_1: Thick film
R51-R53 R55 = R_2512_1: Thick film
R59 R67 = R_0402_1/16W_1%_1: Thick film; Power: 1/16W
R109 = R_NTC_5R_2A_P5mm: 10kΩ 电阻精度:±0.5% 3380K  NTCG163JX103DT1S
SW1 = SW_TH_4P_L6.0W6.0_P3.9_LS6.5: TH 3.9*6.5; BOM_Manufacturer: Yuandi(台湾元迪); Contributor: LCSC
TP40 = TEST-SMD: 测试点/测试环,5017
U1 = U_SPD1179_QFN56: 32-bit ARM CM4 automotives MCU with HV power management, LIN and PDRV; Manufacture: Spintrol
U2 = U_LDO_EQ5430
U3 = U_TJA1044GT/3: CAN transceiver CAN FD
U4 U5 = U_LM2904DT: Manufacturer: ST(意法半导体); Add into BOM: yes; Amplifier Type: General Purpose; Number of Circuits: 2; Gain Bandwidth Product（GBP）: 1.1MHz; Slew Rate（SR）: 0.6 V/us
Y1 = Z_32MHz_SMD: Part_number: AD-CJ13-320001010D05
